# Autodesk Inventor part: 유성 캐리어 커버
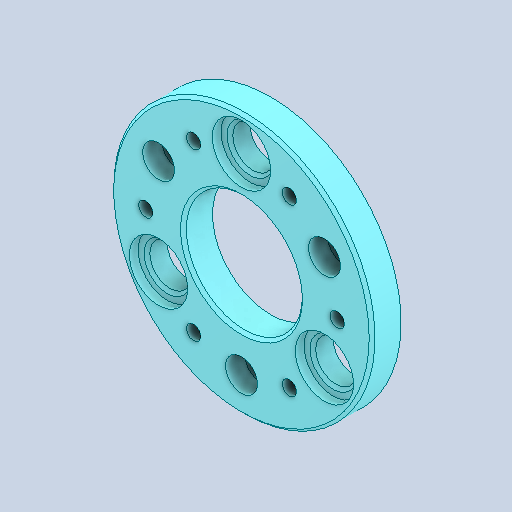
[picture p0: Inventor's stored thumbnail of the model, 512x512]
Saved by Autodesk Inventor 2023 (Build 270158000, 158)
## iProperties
Created: 2026-04
Part Number: 유성 캐리어 커버
Material: 강철, 연강
Document SubType Name: Modeling
Designer: home
Density: 7.85 g/cm^3
Appearance: 기본값
Author: jhkim
Sending System: Autodesk Inventor 2027
Preprocessor: ST-DEVELOPER v20.1
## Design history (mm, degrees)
feature "솔리드1"
node "솔리드2"
